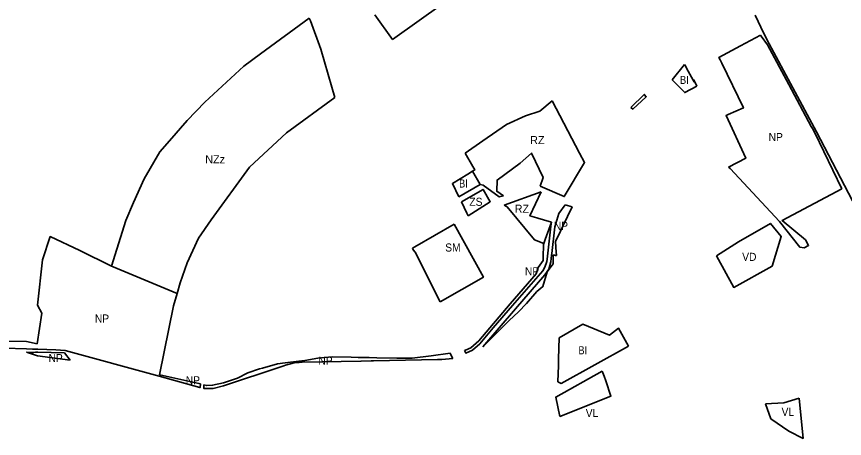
# Model space of a CAD drawing. Extents: x -650971 to -642489, y -1074311 to -1062745.
# Drawn here: x -647426 to -646196, y -1073134 to -1072507 of the extents above; entities that cross this region are included whole.
import ezdxf

# ---------------------------------------------------------------- set-up
doc = ezdxf.new("R2010")
doc.units = 0
doc.header["$LTSCALE"] = 4.8
for name, color, linetype, lineweight in [('18', 7, 'Continuous', 35), ('2', 7, 'Continuous', 35), ('30', 7, 'Continuous', 35), ('34', 7, 'Continuous', 35), ('35', 7, 'Continuous', 35), ('41', 7, 'Continuous', 35), ('46', 7, 'Continuous', 35), ('48', 7, 'Continuous', 35), ('6', 7, 'Continuous', 35), ('62', 7, 'Continuous', 35)]:
    doc.layers.add(name, color=color, linetype=linetype, lineweight=lineweight)

msp = doc.modelspace()

# ---------------------------------------------------------------- linework, layer by layer
at = {"layer": '18'}
for points in [[(-646837.81, -1072851.3), (-646834.08, -1072849.15), (-646775.85, -1072815.39)], [(-646775.85, -1072815.39), (-646732.28, -1072894.29), (-646796.68, -1072930.92)], [(-646796.68, -1072930.92), (-646833.67, -1072857.15), (-646836.5, -1072853.76), (-646837.81, -1072851.3)]]:
    msp.add_lwpolyline(points, dxfattribs=at)
at = {"layer": '2'}
msp.add_line((-646451.458, -1072601.008), (-646433.36, -1072578.45), dxfattribs=at)
for points in [[(-646433.36, -1072578.45), (-646432.57, -1072579.75), (-646427.95, -1072588.07), (-646420.36, -1072601.78), (-646419.02, -1072604.18), (-646419.47, -1072601.31), (-646419.11, -1072602.03), (-646414.77, -1072610.61)], [(-646414.77, -1072610.61), (-646433.024, -1072620.04), (-646451.458, -1072601.008)], [(-646619.48, -1072984.34), (-646584.23, -1072964.22), (-646544.68, -1072980.62), (-646531.46, -1072970.12), (-646516.7, -1072996.65)], [(-646516.7, -1072996.65), (-646616.55, -1073052.21), (-646621.44, -1073049.79), (-646620.71, -1073025.49), (-646620.38, -1073015.9), (-646619.48, -1072984.34)]]:
    msp.add_lwpolyline(points, dxfattribs=at)
msp.add_lwpolyline([(-646768.74, -1072774.78), (-646778.2, -1072755.19), (-646755.1, -1072741.28), (-646748.3, -1072737.01), (-646737.05, -1072756.4)], close=True, dxfattribs=at)
at = {"layer": '30'}
msp.add_lwpolyline([(-646810.77, -1072451.09), (-646790.354, -1072486.136), (-646791.569, -1072487.198), (-646867.283, -1072540.984), (-646893.64, -1072504.45)], dxfattribs=at)
at = {"layer": '34'}
for points in [[(-646618.56, -1073101.42), (-646624.69, -1073072.66), (-646555.79, -1073033.92)], [(-646555.79, -1073033.92), (-646552.79, -1073041.53), (-646550.01, -1073048.55), (-646542.62, -1073071.1), (-646618.56, -1073101.42)], [(-646312.87, -1073082.4), (-646285.77, -1073081.01), (-646262.94, -1073074.15)], [(-646262.94, -1073074.15), (-646257.09, -1073134.01), (-646278.38, -1073123.25), (-646305.18, -1073104.8), (-646312.87, -1073082.4)]]:
    msp.add_lwpolyline(points, dxfattribs=at)
at = {"layer": '35'}
msp.add_lwpolyline([(-646385.86, -1072862.59), (-646353.25, -1072841.63), (-646305.56, -1072814.43), (-646289.63, -1072834.04), (-646303.02, -1072877.74), (-646360.22, -1072909.57)], close=True, dxfattribs=at)
at = {"layer": '41'}
for points in [[(-646765, -1072782.52), (-646732.76, -1072763.81), (-646722.072, -1072782.236), (-646754.96, -1072803.29)], [(-646754.96, -1072803.29), (-646756.92, -1072799.26), (-646765, -1072782.52)]]:
    msp.add_lwpolyline(points, dxfattribs=at)
at = {"layer": '46'}
for points in [[(-647088.4, -1072580.868), (-647063.38, -1072562.42), (-646991.24, -1072509.24)], [(-646991.24, -1072509.24), (-646989.01, -1072513.62), (-646973.68, -1072555.68), (-646957.5, -1072612.09), (-646953.2, -1072627.45)], [(-647284.75, -1072877.79), (-647263.58, -1072809.97), (-647252.29, -1072783.24), (-647236.54, -1072748.09), (-647212.92, -1072708.05), (-647198.77, -1072691.71), (-647172.36, -1072661.69), (-647146.21, -1072634.02), (-647088.4, -1072580.868)], [(-646953.2, -1072627.45), (-647025.04, -1072679.96), (-647079.74, -1072731.1), (-647136.69, -1072808.98), (-647155.72, -1072836.46), (-647172.48, -1072872.92), (-647182.61, -1072902.92), (-647187.445, -1072918.804)], [(-647187.445, -1072918.804), (-647282.31, -1072878.82), (-647284.75, -1072877.79)]]:
    msp.add_lwpolyline(points, dxfattribs=at)
at = {"layer": '48'}
for points in [[(-646171.72, -1072803.51), (-646236.97, -1072678.31), (-646307.6, -1072547.74), (-646315.32, -1072532.01), (-646328.45, -1072504.81)], [(-646377.84, -1072576.29), (-646380.47, -1072571.51), (-646382.41, -1072568.01), (-646350.18, -1072550.59), (-646320.62, -1072534.6)], [(-646320.62, -1072534.6), (-646319.56, -1072536.05), (-646310.01, -1072549.22), (-646278.44, -1072608.07), (-646245.13, -1072670.2), (-646243.32, -1072673.57), (-646239.88, -1072679.99), (-646199.72, -1072763.1)], [(-646367.72, -1072730.68), (-646342.08, -1072717.43), (-646371.66, -1072654.2), (-646368.51, -1072652.81), (-646345.75, -1072642.79), (-646377.84, -1072576.29)], [(-646255.39, -1072850.83), (-646261.97, -1072849.66), (-646292.17, -1072811.6), (-646365.52, -1072733.03), (-646367.72, -1072730.68)], [(-646199.72, -1072763.1), (-646288.27, -1072810.22), (-646253.56, -1072838.8), (-646249.04, -1072847.16), (-646255.39, -1072850.83)], [(-646732.95, -1072998.07), (-646684.36, -1072941.43), (-646640.96, -1072890.83), (-646635.11, -1072882.47), (-646631.89, -1072871.33), (-646630.76, -1072861.61), (-646630.57, -1072859.99), (-646630.45, -1072858.93), (-646625.91, -1072819.66), (-646624.54, -1072814.52), (-646620.27, -1072799.95), (-646610.86, -1072786.74)], [(-646610.86, -1072786.74), (-646603.99, -1072788.9), (-646600.37, -1072790.04)], [(-646600.37, -1072790.04), (-646614.07, -1072818.47), (-646617.596, -1072825.798), (-646625.02, -1072841.21), (-646623.95, -1072857.6), (-646623.71, -1072861.37), (-646623.67, -1072862.03)], [(-646631.08, -1072812.68), (-646631.85, -1072818.45), (-646637.52, -1072867.43), (-646637.92, -1072870.91), (-646640.92, -1072879.6), (-646644.12, -1072884.84), (-646689.13, -1072936.62), (-646717.7, -1072969.5), (-646737.7, -1072993.52), (-646748.51, -1073002.74), (-646758.44, -1073007.19), (-646760.416, -1073003.25)], [(-646642.404, -1072844.195), (-646640.313, -1072838.394), (-646631.08, -1072812.68)], [(-648023.818, -1072955.949), (-648023.495, -1072955.875), (-647811.752, -1072979.4), (-647778.296, -1072982.767), (-647411.293, -1072989.813), (-647395.47, -1072993.25), (-647388.62, -1072948.03), (-647394.87, -1072936.08), (-647387.64, -1072868.69), (-647375.92, -1072833.99), (-647331.82, -1072854.49), (-647284.75, -1072877.79)], [(-646643.445, -1072864.732), (-646642.939, -1072845.68), (-646642.438, -1072844.29), (-646642.39, -1072844.2), (-646642.404, -1072844.195)], [(-646760.416, -1073003.25), (-646758.883, -1073002.885), (-646751.061, -1072999.106), (-646739.241, -1072988.798), (-646692.432, -1072934.135), (-646653.846, -1072889.44), (-646650.798, -1072879.828), (-646643.574, -1072869.57), (-646643.445, -1072864.732)], [(-646623.67, -1072862.03), (-646624.824, -1072861.951), (-646625.96, -1072861.88), (-646628.36, -1072861.71), (-646628.58, -1072869.88), (-646628.7, -1072874.5), (-646637.2, -1072886.57), (-646644.059, -1072908.208), (-646644.069, -1072908.218), (-646652.76, -1072915.66), (-646668.09, -1072933.43), (-646680.07, -1072945.74), (-646693.9, -1072958.84), (-646710.3, -1072975.31), (-646732.95, -1072998.07)], [(-647284.75, -1072877.79), (-647282.31, -1072878.82), (-647187.445, -1072918.804)], [(-647187.445, -1072918.804), (-647192.93, -1072936.82), (-647213.562, -1073039.322), (-647213.218, -1073039.42), (-647154.999, -1073052.287), (-647152.621, -1073052.925)], [(-647153.44, -1073058.06), (-647213.99, -1073041.449), (-647353.78, -1073003.1), (-647367.45, -1073002.47), (-647394.46, -1073001.23), (-647400.55, -1073001.48), (-647402.49, -1073001.41), (-647411.324, -1073001.08), (-647444.42, -1072999.87), (-647497.35, -1072997.93), (-647682.74, -1072990.95), (-647686.14, -1072990.78), (-647778.3, -1072986.29), (-647790.52, -1072985.06), (-647846.85, -1072979.37), (-648014.16, -1072961.36), (-648023.37, -1072960.37), (-648023.818, -1072955.949)], [(-647411.34, -1073005.89), (-647403.05, -1073006.2), (-647400.76, -1073006.29), (-647400.27, -1073006.24), (-647397.74, -1073005.95), (-647395.08, -1073005.64), (-647394.59, -1073005.58), (-647354.76, -1073006.65), (-647346.22, -1073017.52)], [(-647346.22, -1073017.52), (-647394.782, -1073011.002), (-647411.34, -1073005.89)], [(-646902.136, -1073013.834), (-646890.523, -1073014.073), (-646861.07, -1073014.672), (-646838.25, -1073014.938), (-646809.778, -1073011.019), (-646781.703, -1073007.452)], [(-646781.703, -1073007.452), (-646779.55, -1073011.68), (-646777.74, -1073015.29)], [(-647147.85, -1073054.204), (-647143.312, -1073055.421), (-647134.596, -1073054.974), (-647118.513, -1073051.327), (-647097.466, -1073044.268), (-647082.267, -1073036.684), (-647064.784, -1073030.747), (-647060.677, -1073029.351), (-647037.971, -1073023.24), (-647026.763, -1073021.811), (-647006.715, -1073019.236), (-646997.824, -1073018.092), (-646978.077, -1073014.931), (-646956.919, -1073012.775), (-646928.807, -1073013.313), (-646918.156, -1073013.511), (-646902.136, -1073013.834)], [(-646777.74, -1073015.29), (-646793.8, -1073016.61), (-646800.44, -1073016.74), (-646895.76, -1073018.63), (-646899.22, -1073018.7), (-646913.94, -1073018.99), (-646914.54, -1073019), (-647001.66, -1073020.72), (-647006.15, -1073020.99), (-647013.4, -1073021.42), (-647026.54, -1073025.11), (-647028.91, -1073025.91), (-647033.44, -1073027.43), (-647118.27, -1073055.88), (-647134.03, -1073059.94), (-647147.17, -1073059.97), (-647147.43, -1073059.78)], [(-647152.621, -1073052.925), (-647152.96, -1073058.19), (-647153.44, -1073058.06)], [(-647147.43, -1073059.78), (-647147.91, -1073059.64), (-647147.85, -1073054.204)]]:
    msp.add_lwpolyline(points, dxfattribs=at)
msp.add_lwpolyline([(-646513.209, -1072641.935), (-646493.229, -1072622.74), (-646490.11, -1072626.15), (-646510.28, -1072644.42)], close=True, dxfattribs=at)
at = {"layer": '6'}
msp.add_line((-646701.12, -1072787.08), (-646646.12, -1072767.32), dxfattribs=at)
for points in [[(-646697.89, -1072667.65), (-646669.6, -1072654.53), (-646648.27, -1072647.48), (-646629.86, -1072632.07)], [(-646629.86, -1072632.07), (-646589.37, -1072709.83), (-646581.92, -1072723.91), (-646612.11, -1072774.56), (-646647.93, -1072759.01)], [(-646759.491, -1072709.878), (-646732.95, -1072691.68), (-646697.89, -1072667.65)], [(-646748.3, -1072737.01), (-646744.94, -1072734.88), (-646747.87, -1072729.85), (-646759.491, -1072709.878)], [(-646647.93, -1072759.01), (-646643.36, -1072746.04), (-646660.89, -1072709.97), (-646677.39, -1072724.85), (-646711.79, -1072750.02), (-646712.46, -1072766.76), (-646702.45, -1072773.39)], [(-646702.45, -1072773.39), (-646708.65, -1072775.02), (-646732.5, -1072757.63), (-646737.05, -1072756.4), (-646748.3, -1072737.01)], [(-646646.12, -1072767.32), (-646663.07, -1072803.04), (-646653.02, -1072806.07), (-646651.11, -1072806.64), (-646643.01, -1072809.08), (-646631.08, -1072812.68)], [(-646642.404, -1072844.195), (-646656.36, -1072839.08), (-646697.09, -1072790.03), (-646701.12, -1072787.08)], [(-646631.08, -1072812.68), (-646640.313, -1072838.394), (-646642.404, -1072844.195)]]:
    msp.add_lwpolyline(points, dxfattribs=at)

# ---------------------------------------------------------------- texts
at = {"layer": '62'}
for s, width, p in [('BI', 0.85, (-646440, -1072607.167)), ('NP', 0.95, (-646308.335, -1072692.048)), ('BI', 0.85, (-646768.325, -1072761.133)), ('ZS', 0.95, (-646753.085, -1072788.28)), ('NP', 0.95, (-646627.575, -1072824.064)), ('SM', 0.95, (-646788.938, -1072856.245)), ('VD', 0.95, (-646347.605, -1072870.155)), ('NP', 0.95, (-646670.505, -1072891.594)), ('NP', 0.95, (-647309.627, -1072961.756)), ('NP', 0.95, (-647378.505, -1073020.594)), ('BI', 0.85, (-646590.991, -1073009.043)), ('NP', 0.95, (-646977.505, -1073024.594)), ('NP', 0.95, (-647174.505, -1073053.594)), ('VL', 0.95, (-646580.107, -1073102.218)), ('VL', 0.95, (-646289.098, -1073100.515))]:
    msp.add_text(s, height=12, dxfattribs=dict(at, width=width)).set_placement(p)
for s, p in [('RZ', (-646662.725, -1072696.633)), ('NZz', (-647145.58, -1072725.109)), ('RZ', (-646685.725, -1072798.633))]:
    msp.add_text(s, height=12, dxfattribs=at).set_placement(p)

doc.saveas('drawing.dxf')
